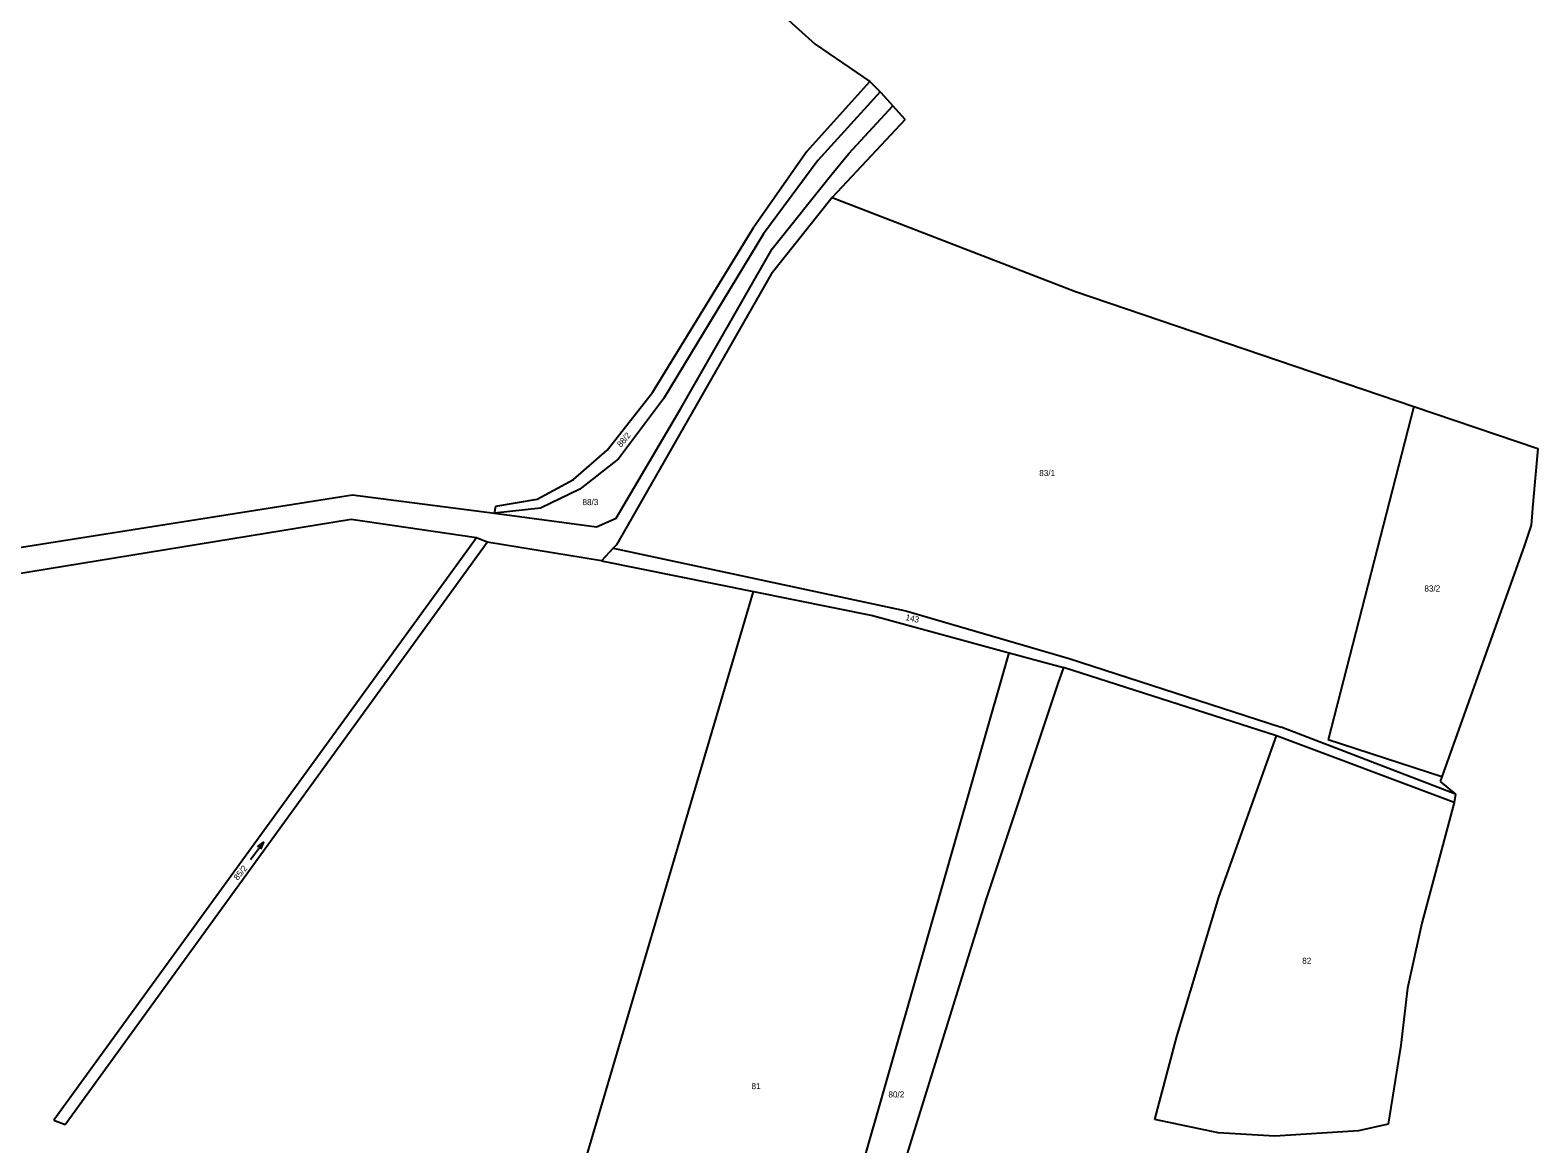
# Model space of a CAD drawing. Extents: x -752500 to -750336, y -1035826 to -1033500.
# Drawn here: x -750986.2 to -750565.4, y -1034562.6 to -1034251.8 of the extents above; entities that cross this region are included whole.
import ezdxf

# ---------------------------------------------------------------- set-up
doc = ezdxf.new("R2010")
doc.units = 0
for name, color, linetype in [('Default', 7, 'Continuous'), ('Hranice kat_území', 7, 'Continuous'), ('Hranice parcel', 7, 'Continuous'), ('Parcelní čísla', 7, 'Continuous'), ('Značky kultur', 7, 'Continuous')]:
    doc.layers.add(name, color=color, linetype=linetype)

# ---------------------------------------------------------------- blocks, each defined once
blk = doc.blocks.new('802')
at = {"layer": 'Default'}
blk.add_line((-3, 0), (3, 0), dxfattribs=at)
blk.add_lwpolyline([(1, 0.5), (3, 0), (1, -0.5)], dxfattribs=at)

msp = doc.modelspace()

# ---------------------------------------------------------------- linework, layer by layer
at = {"layer": 'Hranice kat_území'}
for p, q in [((-750793.52, -1034231.79), (-750767.08, -1034255.78)), ((-750767.08, -1034255.78), (-750751.84, -1034266.14)), ((-750751.84, -1034266.14), (-750748.9, -1034269.06)), ((-750748.9, -1034269.06), (-750748.64, -1034269.34)), ((-750748.64, -1034269.34), (-750745.4, -1034272.94)), ((-750741.99, -1034276.72), (-750745.4, -1034272.94)), ((-750741.99, -1034276.72), (-750762.31, -1034298.57)), ((-750762.31, -1034298.57), (-750694.43, -1034324.77)), ((-750694.43, -1034324.77), (-750599.97, -1034356.85)), ((-750599.97, -1034356.85), (-750565.37, -1034368.6)), ((-750565.37, -1034368.6), (-750566.77, -1034384.15)), ((-750566.77, -1034384.15), (-750567.22, -1034390)), ((-750567.22, -1034390), (-750569.07, -1034395.55)), ((-750569.07, -1034395.55), (-750592.16, -1034460.18)), ((-750697.81, -1034429.72), (-750699.31, -1034434.2)), ((-750638.31, -1034448.72), (-750697.81, -1034429.72)), ((-750699.31, -1034434.2), (-750719.43, -1034494.57)), ((-750654.41, -1034493.79), (-750638.31, -1034448.72)), ((-750592.16, -1034460.18), (-750592.63, -1034461.49)), ((-750592.63, -1034461.49), (-750588.33, -1034465.08)), ((-750588.33, -1034465.08), (-750588.72, -1034467.39)), ((-750588.72, -1034467.39), (-750597.79, -1034501.03)), ((-750719.43, -1034494.57), (-750774.55, -1034672.15)), ((-750666.11, -1034532.68), (-750654.41, -1034493.79)), ((-750597.79, -1034501.03), (-750601.73, -1034519.21)), ((-750601.73, -1034519.21), (-750603.6, -1034535.06)), ((-750672.24, -1034555.87), (-750666.11, -1034532.68)), ((-750603.6, -1034535.06), (-750607.16, -1034557.12)), ((-750654.56, -1034559.6), (-750672.24, -1034555.87)), ((-750638.78, -1034560.45), (-750654.56, -1034559.6)), ((-750615.39, -1034559.04), (-750638.78, -1034560.45)), ((-750607.16, -1034557.12), (-750615.39, -1034559.04))]:
    msp.add_line(p, q, dxfattribs=at)
at = {"layer": 'Hranice parcel'}
for p, q in [((-750769.43, -1034285.67), (-750751.84, -1034266.14)), ((-750748.9, -1034269.06), (-750766.32, -1034288.22)), ((-750757.72, -1034286.28), (-750745.4, -1034272.94)), ((-750769.43, -1034285.67), (-750784.23, -1034306.83)), ((-750762.43, -1034291.98), (-750757.72, -1034286.28)), ((-750766.32, -1034288.22), (-750781.47, -1034308.64)), ((-750779.06, -1034312.87), (-750762.43, -1034291.98)), ((-750762.31, -1034298.57), (-750779.39, -1034319.91)), ((-750812.47, -1034352.97), (-750784.23, -1034306.83)), ((-750781.47, -1034308.64), (-750809.4, -1034354.75)), ((-750804.49, -1034357.19), (-750779.06, -1034312.87)), ((-750779.39, -1034319.91), (-750822.58, -1034395.46)), ((-750825.1, -1034369.07), (-750812.47, -1034352.97)), ((-750822.59, -1034388.01), (-750804.49, -1034357.19)), ((-750809.4, -1034354.75), (-750821.95, -1034371.45)), ((-750599.97, -1034356.85), (-750623.85, -1034449.92)), ((-750834.56, -1034377.19), (-750825.1, -1034369.07)), ((-750821.95, -1034371.45), (-750832.79, -1034379.92)), ((-750844.72, -1034382.74), (-750834.56, -1034377.19)), ((-751060.39, -1034407.52), (-750896.24, -1034381.51)), ((-750896.24, -1034381.51), (-750856.57, -1034386.62)), ((-750856.24, -1034384.69), (-750844.72, -1034382.74)), ((-750832.79, -1034379.92), (-750843.74, -1034385.23)), ((-750856.57, -1034386.62), (-750856.24, -1034384.69)), ((-750843.74, -1034385.23), (-750856.57, -1034386.62)), ((-750856.57, -1034386.62), (-750828.13, -1034390.41)), ((-750896.63, -1034388.35), (-751060.35, -1034415.09)), ((-750861.62, -1034393.54), (-750896.63, -1034388.35)), ((-750828.13, -1034390.41), (-750822.59, -1034388.01)), ((-750861.62, -1034393.54), (-750979.61, -1034556.03)), ((-750976.38, -1034557.25), (-750858.66, -1034394.73)), ((-750858.66, -1034394.73), (-750861.62, -1034393.54)), ((-750826.76, -1034399.92), (-750858.66, -1034394.73)), ((-750822.58, -1034395.46), (-750823.46, -1034396.4)), ((-750823.46, -1034396.4), (-750826.76, -1034399.92)), ((-750826.76, -1034399.92), (-750784.34, -1034408.5)), ((-750823.46, -1034396.4), (-750741.77, -1034413.86)), ((-750859.51, -1034662.8), (-750784.34, -1034408.5)), ((-750784.34, -1034408.5), (-750751.1, -1034415.2)), ((-750751.1, -1034415.2), (-750712.91, -1034425.61)), ((-750741.77, -1034413.86), (-750696.19, -1034427.22)), ((-750783.18, -1034670.85), (-750712.91, -1034425.61)), ((-750712.91, -1034425.61), (-750697.81, -1034429.72)), ((-750696.19, -1034427.22), (-750636.99, -1034446.31)), ((-750588.72, -1034467.39), (-750638.31, -1034448.72)), ((-750588.33, -1034465.08), (-750636.99, -1034446.31)), ((-750592.16, -1034460.18), (-750623.85, -1034449.92)), ((-750979.61, -1034556.03), (-750976.38, -1034557.25))]:
    msp.add_line(p, q, dxfattribs=at)

# ---------------------------------------------------------------- block references
at = {"layer": 'Značky kultur', "rotation": 52.654821}
msp.add_blockref('802', (-750922.91, -1034480.85), dxfattribs=at)

# ---------------------------------------------------------------- texts
at = {"layer": 'Parcelní čísla'}
for s, rotation, p in [('88/2', 50.478, (-750821.26, -1034368.38)), ('143', 347.9, (-750741.97, -1034416.44)), ('85/2', 50.592, (-750928.27, -1034489.22))]:
    msp.add_text(s, height=1.7, rotation=rotation, dxfattribs=at).set_placement(p)
for s, p in [('83/1', (-750704.53, -1034376.27)), ('88/3', (-750832.03, -1034384.38)), ('83/2', (-750597.04, -1034408.5)), ('82', (-750631.13, -1034512.39)), ('81', (-750784.85, -1034547.37)), ('80/2', (-750746.64, -1034549.68))]:
    msp.add_text(s, height=1.7, dxfattribs=at).set_placement(p)

doc.saveas('drawing.dxf')
